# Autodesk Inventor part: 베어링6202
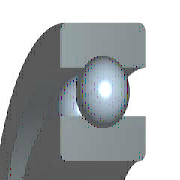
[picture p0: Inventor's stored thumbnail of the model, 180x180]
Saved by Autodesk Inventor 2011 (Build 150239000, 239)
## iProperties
IsCustomPart: 0
Company: 한국ATC센터
Created: 2014-12
Part Number: 베어링6202
Material: 강, 연강
Description: 깊은 그루브 볼 베어링
Document SubType Name: Modeling
Standard: KS B 2023
Designer: KYOUNG IL JANG
Standards Organization: KS
Language: ko-KR
Size Designation: 6202 - 15 x 35 x 11
Categories: <MemberInstance><Categories><Category DisplayName="샤프트 부품" InternalName="7f7aeb1f-a693-4053-b835-cee3144e0d98" Mnemonic="SHFT"><Category DisplayName="베어링" Inter
Density: 7.86 g/cm^3
Mass: 45.8725 g
Surface Area: 51.5584 cm^2
Volume: 5.83619 cm^3
Author: KYOUNG IL JANG
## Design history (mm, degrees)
revolve "본체" stored, may be unused: angle "d6" = 90 deg
revolve "볼" stored, may be unused: angle "d7" = 90 deg
pattern_circular "IDS_ARRAYBALL[SIMPL:T]" dims angle "d3" = 360 deg
body "Solid1"
sketch "스케치" dims "d0" = 5.2 (= -0.26 x WD + 0.26 x BD)
  geometry: L1 (2.9, 12.5)-(8.1, 12.5); L2 (5.5, 12.5)-(5.5, 9.9); L3 (5.5, 12.5)-(5.5, 15.1); L4 (3.568, 10.76)-(0, 10.76); L5 (0, 7.5)-(11, 7.5); L6 (3.568, 14.24)-(0, 14.24); L7 (0, 17.5)-(11, 17.5); L8 (11, 7.5)-(11, 10.76); L9 (7.432, 10.76)-(11, 10.76); L10 (7.432, 14.24)-(11, 14.24); L11 (11, 17.5)-(11, 14.24); L12 (-1.4, 0)-(8.4, 0) reference; L13 (0, -0.3)-(0, 5.3) reference
  constraints: 22 end point, 4 point on line, 2 collinear, 2 perpendicular, 2 symmetric about line, 1 midpoint, 1 parallel, 14 other
  dimensions: "d9" = 15 diameter of L5 L12 (= WD); "d11" = 35 diameter of L7 L12 (= BD); "d12" = 11 distance between parallel lines of L8 L13 (= KB); "d13" = 21.52 diameter of L9 L12 (= 0.326 x BD + 0.674 x WD)
fillet "모깎기1" dims "d1" = 0.6 (= KRS)
other parameters: "WD" = 15 [user parameter; used in 5 equation terms], "BD" = 35 [user parameter; used in 5 equation terms], "KB" = 11 [user parameter; used in 1 equation term], "KRS" = 0.6 [user parameter; used in 1 equation term], "d4" = 0, "d5" = 0, "d8" = 0, "d14" = 0, "d15" = 0, "BBA" = 0 [user parameter], "BC0" = 3750000 [user parameter], "BC" = 7800000 [user parameter], "BR" = 17.5 (= 0.5 x BD) [user parameter], "WR" = 7.5 (= 0.5 x WD) [user parameter]
